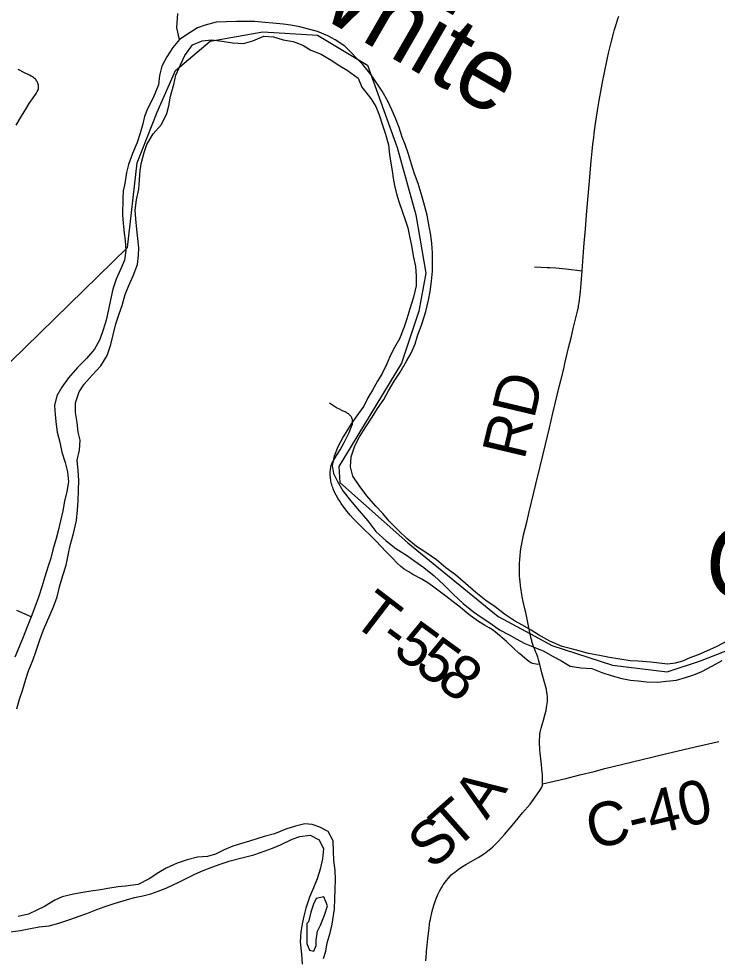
# Model space of a CAD drawing. Extents: x 1451455 to 1749751, y 218250 to 574981.
# Drawn here: x 1570249 to 1575046, y 361334 to 367778 of the extents above; entities that cross this region are included whole.
import ezdxf

# ---------------------------------------------------------------- set-up
doc = ezdxf.new("R2010")
doc.units = 0
for name, color, linetype in [('GM_X_County_Road', 7, 'Continuous'), ('GM_X_County_Road_Text', 7, 'Continuous'), ('GM_X_Major_River', 7, 'Continuous'), ('GM_X_Major_River_Text', 7, 'Continuous'), ('GM_X_Minor_River', 7, 'Continuous'), ('GM_X_Township', 7, 'Continuous'), ('GM_X_Township_Road', 7, 'Continuous'), ('GM_X_Township_Road_Text', 7, 'Continuous')]:
    doc.layers.add(name, color=color, linetype=linetype)

msp = doc.modelspace()

# ---------------------------------------------------------------- linework, layer by layer
at = {"layer": 'GM_X_County_Road'}
for points in [[(1574117.6, 366048), (1574129.7, 366208.3), (1574132, 366238.3), (1574140.5, 366333.9), (1574149, 366431.5), (1574166.7, 366638), (1574180.6, 366800.2), (1574186.9, 366870.1), (1574192.2, 366918.3), (1574197.5, 366963), (1574200.9, 366990.4), (1574209.8, 367060.3), (1574224.9, 367161.1), (1574234, 367216.4), (1574250.2, 367304.9), (1574260.1, 367354.7), (1574266.5, 367386.3), (1574292.9, 367510.9), (1574299.9, 367541.4), (1574318, 367615.4), (1574336.2, 367687.5), (1574341, 367705.5), (1574348.6, 367732), (1574355.5, 367754.1), (1574363.8, 367778.2), (1574370.3, 367796.1)], [(1573771.8, 363509), (1573768.4, 363522.6), (1573756.4, 363575.3), (1573749.3, 363610.3), (1573730.9, 363700.2), (1573724.4, 363727.4), (1573713.2, 363776.3), (1573706.9, 363808.2), (1573703.5, 363826.8), (1573701.5, 363839.4), (1573698.9, 363857), (1573697.3, 363868.9), (1573694.8, 363888.4), (1573692, 363912), (1573689.8, 363932.8), (1573688.5, 363950.7), (1573687.7, 363966.5), (1573687.3, 363981.9), (1573687.1, 364004.3), (1573688.6, 364039.6), (1573690.2, 364062.6), (1573692.6, 364093.7), (1573695.8, 364120.9), (1573700.2, 364151.1), (1573703.8, 364173.2), (1573710.6, 364209.6), (1573715.9, 364234.5), (1573737.3, 364320.4), (1573754.5, 364392.3), (1573801.2, 364583.3), (1573830.2, 364702.9), (1573866.3, 364854.8), (1573894.1, 364969.8), (1573917.8, 365069.4), (1573963.8, 365260.9), (1573971.9, 365295.1), (1573991.3, 365375.4), (1573999.3, 365410.9), (1574025.1, 365518.1), (1574042, 365588.1), (1574057.4, 365651.7), (1574080.2, 365742.7), (1574086.9, 365771.3), (1574089.4, 365783), (1574092.2, 365797.1), (1574094.2, 365808.5), (1574097.4, 365828.7), (1574100.9, 365848.9), (1574105.7, 365884.4), (1574108, 365905.7), (1574111.7, 365959.8), (1574117.6, 366048)], [(1573826.9, 363344.4), (1573819.1, 363375.5), (1573813.3, 363395.3), (1573808.6, 363409), (1573804.3, 363420.3), (1573798.6, 363434.1), (1573792.9, 363447.2), (1573787, 363461.4), (1573782, 363474.8), (1573777.5, 363488.1), (1573773.5, 363502.6), (1573771.8, 363509)], [(1573846.9, 362525.7), (1573846.6, 362544.5), (1573845.9, 362567.4), (1573844.8, 362588.1), (1573843.8, 362604.1), (1573841.8, 362626.1), (1573838.5, 362656.7), (1573830.9, 362734.4), (1573828.6, 362758.4), (1573826.9, 362777.6), (1573826.2, 362790.6), (1573825.7, 362805), (1573825.6, 362812.2), (1573826, 362828.2), (1573827, 362846.5), (1573828.5, 362863.4), (1573830.8, 362878.7), (1573832.7, 362888.3), (1573837, 362906.7), (1573841.5, 362923.3), (1573852.5, 362961.2), (1573864.8, 363004.4), (1573870.3, 363027.8), (1573874.3, 363048.1), (1573876.7, 363063.1), (1573878.4, 363076.9), (1573879.4, 363089.8), (1573880, 363102.5), (1573880, 363111.4), (1573879.8, 363124.7), (1573878.7, 363137.4), (1573876.7, 363153), (1573872.8, 363173.3), (1573862.8, 363212.8), (1573841.1, 363287.7), (1573826.9, 363344.4)], [(1573846.9, 362525.7), (1574006, 362562), (1574101.6, 362585.4), (1574200.3, 362610.2), (1574273.2, 362628.9), (1574396.8, 362660), (1574530.8, 362692.2), (1574597.8, 362708.1), (1574632.9, 362716.5), (1574699.6, 362732.7), (1574807.6, 362759), (1574893.9, 362778.3), (1575057.1, 362814.2)], [(1573421.6, 362030.4), (1573446.5, 362046), (1573470.6, 362063.4), (1573488.6, 362077.9), (1573504.3, 362091.7), (1573517.9, 362104.6), (1573543.2, 362130.5), (1573584.9, 362177.1), (1573648.5, 362252.4), (1573709.5, 362325.3), (1573760.2, 362385.7), (1573784.4, 362417), (1573810.6, 362455.1), (1573831.4, 362486.2), (1573838.3, 362497.9), (1573842.9, 362507.9), (1573845.6, 362516.4), (1573846.9, 362525.7)], [(1573045.3, 361309.2), (1573049.1, 361361.5), (1573050, 361374.6), (1573051.7, 361394.2), (1573058.3, 361462.1), (1573067, 361532.8), (1573070.5, 361559.8), (1573073.3, 361579.5), (1573075.7, 361592.7), (1573078.7, 361608.3), (1573083, 361628.3), (1573088.3, 361649.5), (1573100, 361690.1), (1573113.8, 361729.9), (1573130.4, 361768.6), (1573139.5, 361787.2), (1573147.9, 361803.3), (1573156.4, 361817.6), (1573164.8, 361831), (1573172.9, 361843.2), (1573183.5, 361857.5), (1573199.7, 361877.7), (1573209.4, 361888.7), (1573219.8, 361899.2), (1573230.6, 361909.2), (1573242.8, 361919.1), (1573254.9, 361928.2), (1573267.6, 361937.3), (1573289.2, 361951.7), (1573319.7, 361970.5), (1573404.7, 362019.8), (1573421.6, 362030.4)]]:
    msp.add_lwpolyline(points, dxfattribs=at)
at = {"layer": 'GM_X_Major_River'}
for points in [[(1572744.4, 367281.3), (1572669.8, 367392.4), (1572611.2, 367463.4), (1572489.6, 367589.6), (1572422.5, 367632.8), (1572371.1, 367661.7), (1572301.8, 367691), (1572238.2, 367708.1), (1572178.5, 367723.1), (1572116.8, 367734.2), (1572065, 367741.1), (1571993.3, 367748.3), (1571941.4, 367753.3), (1571867.7, 367760.5), (1571815.7, 367759.4), (1571743.8, 367758.7), (1571673.9, 367757.9), (1571606, 367755.1), (1571529.7, 367734.4), (1571477.4, 367715.3), (1571426.9, 367684.1), (1571354.2, 367635.4), (1571307.3, 367582.2), (1571266.1, 367516.8), (1571231, 367453.4), (1571215.9, 367389.6), (1571208.7, 367323.7)], [(1571314.6, 367325.9), (1571327.8, 367391.7), (1571361, 367461.2), (1571390.1, 367526.7), (1571443.4, 367599.8), (1571509.8, 367626.7), (1571573.8, 367633.6), (1571645.5, 367624.3), (1571717.2, 367613.1), (1571793, 367607.8), (1571857.3, 367626.6), (1571931.7, 367659.4), (1571997.6, 367654.2), (1572065.1, 367633), (1572134.8, 367621.8), (1572200.2, 367596.7), (1572255.5, 367563.7), (1572324.9, 367534.5), (1572394, 367493.2), (1572453.2, 367454.2), (1572504.6, 367425.3), (1572579.5, 367369.9), (1572604.3, 367309.5)], [(1571208.7, 367323.7), (1571172, 367235.5), (1571134.5, 367160.1), (1571113.6, 367108.4), (1571100.6, 367056.6), (1571083.4, 366992.8), (1571062.2, 366929.1), (1571030.8, 366853.6), (1571003.4, 366778), (1570990.3, 366722.1), (1570977, 366648.3), (1570966, 366596.4), (1570963, 366544.4), (1570960.9, 366430.2), (1570965.9, 366376.1), (1570972.6, 366305.9), (1570979.7, 366255.7), (1570984.5, 366187.5), (1570975.3, 366121.6), (1570948, 366056), (1570918.8, 365990.4), (1570895.5, 365922.7), (1570880.1, 365848.9), (1570864.9, 365781.1), (1570849.5, 365709.3), (1570828.3, 365641.5), (1570805, 365575.9), (1570769.8, 365508.4), (1570714.5, 365445.3), (1570653.4, 365384.3), (1570592, 365313.3), (1570544.7, 365248.1), (1570511.6, 365188.6), (1570494.4, 365122.8), (1570499.2, 365058.7), (1570506, 364992.5), (1570513, 364940.2), (1570531.8, 364869.8), (1570544.5, 364801.5), (1570567.2, 364731), (1570584.1, 364666.6), (1570590.8, 364598.4), (1570579.6, 364532.5), (1570564.3, 364464.7), (1570551.1, 364398.8), (1570535.9, 364331), (1570520.6, 364261.2), (1570505.6, 364209.4), (1570484.1, 364131.7), (1570469, 364073.8), (1570452, 364020.1), (1570426.5, 363938.4), (1570409.5, 363884.6), (1570386, 363807), (1570358.7, 363737.4), (1570333.5, 363671.7), (1570308.2, 363602.1), (1570278.9, 363532.5), (1570251.6, 363464.9), (1570222.3, 363395.3)], [(1570235.8, 363040.6), (1570255, 363106.3), (1570274.1, 363166.1), (1570297.6, 363243.8), (1570316.7, 363301.5), (1570348.1, 363379), (1570369.2, 363438.8), (1570394.6, 363512.4), (1570419.9, 363582), (1570442.9, 363633.7), (1570463.9, 363687.4), (1570488.9, 363741), (1570512.2, 363808.7), (1570529.5, 363876.5), (1570553, 363956.2), (1570574.3, 364025.9), (1570589.8, 364105.7), (1570602.8, 364161.6), (1570626.3, 364243.2), (1570646, 364333), (1570653.4, 364407), (1570656.5, 364467), (1570659.8, 364541.1), (1570661.1, 364607.1), (1570658.3, 364675.3), (1570649.6, 364747.5), (1570666.9, 364815.3), (1570670.2, 364885.3), (1570657.2, 364939.7), (1570650.4, 365005.9), (1570639.6, 365074.2), (1570638.9, 365140.3), (1570664.3, 365215.9), (1570699.3, 365269.4), (1570752.5, 365330.5), (1570813.7, 365395.5), (1570857.1, 365466.8), (1570880.5, 365540.5), (1570897.7, 365608.3), (1570917.1, 365684), (1570938.4, 365751.7), (1570959.5, 365809.4), (1570980.9, 365885.1), (1571006.1, 365946.8), (1571035.3, 366012.3), (1571064.8, 366089.9), (1571072, 366155.9), (1571072.9, 366205.9), (1571068.1, 366270.1), (1571061.2, 366332.3), (1571052.5, 366404.6), (1571049.6, 366464.7), (1571056.9, 366534.6), (1571074.3, 366608.4), (1571079.5, 366672.4), (1571082.7, 366738.5), (1571091.7, 366790.4), (1571111, 366860.1), (1571128, 366915.9), (1571173.4, 366987.2), (1571228.6, 367052.3), (1571266.1, 367127.7), (1571281, 367179.5), (1571292.3, 367247.4), (1571314.6, 367325.9)], [(1572604.3, 367309.5), (1572667.4, 367230.6), (1572700.4, 367175.9), (1572723.4, 367119.5), (1572748.1, 367048.9), (1572767, 366986.5), (1572787.6, 366912), (1572796.4, 366845.8), (1572805.3, 366787.5), (1572814.4, 366735.3), (1572819.4, 366683.1), (1572828.5, 366632.9), (1572843.5, 366576.5), (1572860.5, 366524.2), (1572881.3, 366457.7), (1572902.3, 366397.2), (1572921.3, 366342.8), (1572934, 366274.5), (1572947.1, 366222.2), (1572957.8, 366149.9), (1572974.4, 366077.5), (1572979.2, 366011.3), (1572978, 365945.3), (1572960.5, 365865.5), (1572935, 365785.8), (1572913.8, 365718.1), (1572894.6, 365656.4), (1572863.2, 365580.8), (1572830.1, 365521.3), (1572803.1, 365467.8), (1572777.9, 365408.1), (1572744.7, 365342.6), (1572713.7, 365289.1), (1572678.5, 365227.7), (1572645.5, 365174.2), (1572618.4, 365118.6), (1572583.5, 365067.2), (1572532.1, 364996), (1572476.4, 364906.9), (1572441.1, 364839.4), (1572415.9, 364775.8), (1572400.7, 364710), (1572411.7, 364655.7), (1572434.8, 364605.2), (1572475.6, 364536.4), (1572526.4, 364469.4), (1572587.2, 364400.2), (1572646, 364331), (1572700.7, 364257.9), (1572771.5, 364192.6), (1572838.7, 364141.3), (1572917.8, 364089.8), (1572969.2, 364052.8), (1573030.4, 364009.7), (1573101.4, 363952.3), (1573168.4, 363891), (1573235.2, 363823.7), (1573300.2, 363762.5), (1573373.2, 363705.1), (1573424.6, 363670.1), (1573491.8, 363624.8), (1573551.1, 363581.7), (1573616.5, 363548.5), (1573670, 363517.5), (1573723.5, 363488.5), (1573793.1, 363461.2), (1573854.7, 363436), (1573914.1, 363400.9), (1573971.6, 363371.8), (1574035, 363332.6), (1574108.8, 363321.3), (1574184.8, 363315.9), (1574254.4, 363288.6), (1574324, 363265.3), (1574389.8, 363248.1), (1574449.6, 363237), (1574503.6, 363232.1), (1574561.5, 363225), (1574637.6, 363223.6), (1574697.7, 363228.5), (1574765.9, 363237.3), (1574828.3, 363254.2), (1574884.7, 363273.2), (1574941.2, 363296.3)], [(1574856.8, 363389.9), (1574806.4, 363366.8), (1574756.1, 363353.7), (1574705.9, 363346.6), (1574648, 363353.6), (1574590, 363360.7), (1574502.1, 363366.3), (1574448.1, 363369.2), (1574364.2, 363382.8), (1574306.3, 363391.8), (1574238.5, 363405.1), (1574162.7, 363420.5), (1574104.9, 363435.5), (1574035.2, 363454.8), (1573981.4, 363467.8), (1573896, 363505.4), (1573818.7, 363548.8), (1573767.3, 363579.8), (1573707.8, 363614.9), (1573654.3, 363643.9), (1573585.1, 363689.2), (1573520, 363740.5), (1573456.7, 363783.7), (1573387.7, 363839), (1573316.7, 363900.3), (1573247.7, 363959.7), (1573182.6, 364008.9), (1573117.5, 364062.2), (1573044.4, 364113.5), (1572981.1, 364154.8), (1572914, 364210), (1572857, 364265.1), (1572794.1, 364328.3), (1572749, 364381.2), (1572701.9, 364432.1), (1572639.1, 364501.4), (1572586.4, 364572.4), (1572543.5, 364637.3), (1572526.7, 364701.7), (1572531.9, 364769.7), (1572557.4, 364845.3), (1572588.5, 364906.8), (1572633.8, 364976.1), (1572675.1, 365041.5), (1572712.2, 365102.9), (1572755.4, 365164.2), (1572788.5, 365223.7), (1572827.8, 365289.1), (1572869, 365352.4), (1572912.4, 365427.7), (1572943.5, 365483.2), (1572970.7, 365546.8), (1572987.7, 365600.6), (1573017.2, 365680.2), (1573044.8, 365767.8), (1573062.3, 365845.6), (1573073.4, 365905.5), (1573082.7, 365975.4), (1573090, 366045.4), (1573091.1, 366107.5), (1573090.3, 366171.5), (1573085.5, 366235.7), (1573078.5, 366291.9), (1573067.6, 366352.2), (1573053, 366430.6), (1573030.5, 366515.1), (1573013.7, 366577.5), (1572993, 366648), (1572966.1, 366712.5), (1572945.4, 366781), (1572924.6, 366847.5), (1572901.8, 366916), (1572882.7, 366966.4), (1572861.9, 367030.8), (1572837, 367095.4), (1572812.1, 367153.9), (1572783.1, 367212.5), (1572744.4, 367281.3)], [(1575117.3, 363507.4), (1575042.4, 363466.7), (1574971.8, 363435.9), (1574915.3, 363410.9), (1574856.8, 363389.9)], [(1574941.2, 363296.3), (1575014, 363335), (1575078.7, 363371.9)], [(1572342.3, 361324.3), (1572357.3, 361376.1), (1572368.3, 361432), (1572387.6, 361501.8), (1572400.7, 361561.6), (1572416.7, 361665.5), (1572420, 361735.5), (1572421.2, 361801.6), (1572424.4, 361865.6), (1572421.6, 361931.8), (1572412.8, 361998), (1572410, 362062.1), (1572409.3, 362132.2), (1572374.4, 362197), (1572316.9, 362228), (1572265.2, 362245), (1572213.2, 362249.9), (1572150.9, 362235), (1572084.4, 362212.2), (1572005.8, 362181.6), (1571935.3, 362162.8), (1571885, 362147.7), (1571834.6, 362130.6), (1571772.2, 362111.7), (1571719.9, 362096.6), (1571659.4, 362071.7), (1571600.8, 362042.7), (1571544.4, 362025.7), (1571476.3, 362020.9), (1571405.8, 362002.1), (1571337.4, 361979.3), (1571262.6, 361944.6), (1571212.1, 361915.5), (1571145.2, 361872.6), (1571070.4, 361833.9), (1570982.1, 361821.5), (1570932, 361818.4), (1570861.7, 361805.6), (1570811.4, 361796.5), (1570743.2, 361787.7), (1570689, 361778.7), (1570624.7, 361765.8), (1570548.3, 361749.2), (1570497.8, 361726), (1570425, 361683.3), (1570374.4, 361656.2), (1570315.9, 361629.2), (1570245.5, 361614.4)], [(1570191.5, 361507.2), (1570261.7, 361518), (1570318, 361529), (1570390.3, 361541.7), (1570458.6, 361550.5), (1570524.9, 361567.3), (1570599.5, 361592), (1570664, 361614.9), (1570716.4, 361634), (1570784.9, 361660.8), (1570835.3, 361679.9), (1570903.8, 361702.7), (1570990.3, 361727.2), (1571044.7, 361744.2), (1571101, 361755.2), (1571155.3, 361770.3), (1571205.7, 361787.4), (1571266.2, 361810.4), (1571349, 361848.9), (1571407.6, 361879.9), (1571458.1, 361905), (1571514.6, 361930.1), (1571575.1, 361953), (1571631.6, 361974), (1571700, 361994.8), (1571780.5, 362017.4), (1571863, 362038), (1571941.5, 362064.6), (1571991.9, 362081.7), (1572046.4, 362104.7), (1572127.2, 362145.3), (1572179.6, 362162.4), (1572249.8, 362173.2), (1572311.3, 362140), (1572342.2, 362077.4), (1572334.9, 362009.4), (1572319.6, 361939.6), (1572298.3, 361871.9), (1572273.2, 361810.2), (1572246, 361746.6), (1572220.6, 361671), (1572207.5, 361615.2), (1572194.6, 361563.3), (1572185.5, 361507.4), (1572182.3, 361439.4), (1572190.7, 361355.1), (1572195.5, 361286.9)], [(1572226.6, 361564.8), (1572227.1, 361484.6), (1572228.1, 361428.5), (1572245.3, 361382.1), (1572275.2, 361375.6), (1572291.9, 361413.4), (1572290.6, 361451.4), (1572301.7, 361513.3), (1572322.5, 361553), (1572349.8, 361622.6), (1572369, 361686.3), (1572344.1, 361748.9)], [(1572344.1, 361748.9), (1572291.9, 361737.8), (1572273.1, 361698.1), (1572256.1, 361644.3), (1572238.8, 361576.5), (1572226.6, 361564.8)]]:
    msp.add_lwpolyline(points, dxfattribs=at)
at = {"layer": 'GM_X_Minor_River'}
for points in [[(1571354.2, 367635.4), (1571335.1, 367716.7), (1571342.7, 367814.6)], [(1570333.8, 363672.4), (1570236.6, 363714)]]:
    msp.add_lwpolyline(points, dxfattribs=at)
at = {"layer": 'GM_X_Township'}
msp.add_lwpolyline([(1568987.4, 364245.4), (1570997.2, 366208.8), (1571063.4, 366788.4), (1571199.8, 367137.3), (1571326.2, 367422.5), (1571562.8, 367625.4), (1571925.9, 367688.4), (1572301, 367666), (1572643.9, 367459.1), (1572848.5, 366894.7), (1572976.9, 366431.5), (1573045.1, 366032.4), (1572996.9, 365769.7), (1572878.6, 365412.7), (1572447.3, 364702.8), (1572455.3, 364594.5), (1572920.7, 364179.4), (1573542.4, 363674.1), (1573792.7, 363538.7), (1573909.5, 363475.5), (1574326.6, 363339.2), (1574701.7, 363293.1), (1574930.4, 363369.3), (1575393.7, 363549.8)], dxfattribs=at)
msp.add_lwpolyline([(1568987.4, 364245.4), (1570997.2, 366208.8), (1571063.4, 366788.4), (1571199.8, 367137.3), (1571326.2, 367422.5), (1571562.8, 367625.4), (1571925.9, 367688.4), (1572301, 367666), (1572643.9, 367459.1), (1572848.5, 366894.7), (1572976.9, 366431.5), (1573045.1, 366032.4), (1572996.9, 365769.7), (1572878.6, 365412.7), (1572447.3, 364702.8), (1572455.3, 364594.5), (1572920.7, 364179.4), (1573542.4, 363674.1), (1573792.7, 363538.7), (1573909.5, 363475.5), (1574326.6, 363339.2), (1574701.7, 363293.1), (1574930.4, 363369.3), (1575393.7, 363549.8)], dxfattribs=at)
at = {"layer": 'GM_X_Township_Road'}
for points in [[(1570232.6, 367048), (1570268.9, 367110.2), (1570285.9, 367139.7), (1570297.1, 367158.3), (1570321.3, 367197.3), (1570331.9, 367213), (1570343.7, 367229.6), (1570368.7, 367264.2), (1570376.8, 367278.5), (1570382.5, 367289.6), (1570384, 367297.7), (1570384.8, 367303.4), (1570385.2, 367310.7), (1570385, 367316.4), (1570384.4, 367323.3), (1570382.7, 367330.2), (1570380.9, 367335.8), (1570378.5, 367341.6), (1570375.3, 367348), (1570372.1, 367353), (1570367.9, 367358.8), (1570363.9, 367363.3), (1570357.9, 367368.9), (1570351.6, 367374.1), (1570343.6, 367379.7), (1570335.1, 367384.9), (1570324.1, 367391), (1570289.3, 367407.5), (1570245.5, 367430.9)], [(1573791.6, 366075.9), (1573879.1, 366070.7), (1573899.7, 366069.7), (1573936.7, 366067.4), (1573960.8, 366065.4), (1574005.3, 366060.8), (1574117.6, 366048)], [(1572388.4, 364642.8), (1572388.2, 364649.8), (1572388.4, 364658.9), (1572388.8, 364668.1), (1572389.7, 364680), (1572390.6, 364687.2), (1572391.8, 364695.6), (1572393.1, 364703.2), (1572394.9, 364710.6), (1572396.6, 364715.8), (1572398.8, 364721), (1572402.5, 364728.4), (1572406.2, 364735.6), (1572432.3, 364778.2), (1572457.3, 364818.6), (1572470.7, 364842.4), (1572484.2, 364868), (1572502.4, 364904.1), (1572517.2, 364936.2), (1572530.6, 364966.7), (1572535, 364977.8), (1572538.5, 364988.2), (1572540.4, 364995), (1572541.4, 365000.9), (1572542, 365006.2), (1572542.2, 365010.6), (1572542, 365015.9), (1572541.4, 365020.5), (1572540.1, 365026.5), (1572538.4, 365032.1), (1572536.3, 365038), (1572534, 365042.4), (1572531.5, 365046.6), (1572528.4, 365050.9), (1572525.8, 365054.1), (1572523.1, 365056.9), (1572520.5, 365059.6), (1572517.1, 365062.4), (1572513.2, 365065.3), (1572507.8, 365068.8), (1572502.9, 365071.6), (1572498.6, 365073.9), (1572489.7, 365078.2), (1572478.2, 365083.4), (1572466.9, 365088.9), (1572452, 365096.4), (1572431.6, 365107.8), (1572384, 365137.6)], [(1573567.1, 363530.1), (1573559.7, 363536.9), (1573539.7, 363553.5), (1573522, 363567.5), (1573511.3, 363575.5), (1573502.8, 363581.7), (1573491.8, 363588.5), (1573479.3, 363596.5), (1573448.5, 363615), (1573406.6, 363639.9), (1573391.1, 363650.2), (1573374.2, 363662.2), (1573340.5, 363688.3), (1573282.2, 363736.1), (1573181.8, 363814.3), (1573128.1, 363855.5), (1573091.4, 363882.9), (1573058.7, 363904.8), (1573036.1, 363918.8), (1573016.6, 363930.3), (1572956.6, 363963.1), (1572927.6, 363979.6), (1572912.4, 363988.7), (1572897, 363998.5), (1572873.9, 364016.6), (1572847.3, 364041.1), (1572817.4, 364071.3), (1572797.3, 364092.4), (1572773, 364118), (1572701, 364193.2), (1572661.6, 364232.4), (1572624.1, 364269.1), (1572598.6, 364294.7), (1572546.9, 364347.2), (1572526.1, 364369.8), (1572504.8, 364395.4), (1572488.8, 364415.8), (1572463.6, 364449.6), (1572453.6, 364464.8), (1572443.2, 364481.8), (1572429.4, 364506.8), (1572418, 364528.6), (1572413.1, 364539.2), (1572408.6, 364549.6), (1572405.1, 364558.7), (1572401.6, 364568.5), (1572399, 364577.1), (1572396.9, 364585.4), (1572394.9, 364593.9), (1572393.2, 364602.4), (1572391.6, 364611.6), (1572390.2, 364621.1), (1572389.2, 364630.3), (1572388.5, 364641), (1572388.4, 364642.8)], [(1573683.2, 363422.7), (1573648.3, 363454.3), (1573598.2, 363501.5), (1573567.1, 363530.1)], [(1573826.9, 363344.4), (1573803.5, 363346.7), (1573788.3, 363348.9), (1573779.8, 363350.7), (1573776.2, 363351.7), (1573772.5, 363353), (1573766.3, 363355.8), (1573759.8, 363360.2), (1573753.2, 363365.2), (1573724.8, 363387.4), (1573687.2, 363419.1), (1573683.2, 363422.7)]]:
    msp.add_lwpolyline(points, dxfattribs=at)

# ---------------------------------------------------------------- texts
at = {"layer": 'GM_X_County_Road_Text'}
for s, rotation, p in [('RD', 76.67551, (1573720.7, 364742.4)), ('A', 55.59877, (1573462.7, 362271.4)), ('C-40', 13.54901, (1574186.3, 362071.6)), ('T', 41.51146, (1573241.5, 362062.5)), ('S', 41.5558, (1573090.1, 361928.2))]:
    msp.add_text(s, height=300, rotation=rotation, dxfattribs=at).set_placement(p)
at = {"layer": 'GM_X_Major_River_Text'}
for s, height, rotation, p in [('White', 500.02, 329.99559, (1572039.8, 367953.3)), ('Oak', 500, 354.99995, (1574948.3, 363814.8))]:
    msp.add_text(s, height=height, rotation=rotation, dxfattribs=at).set_placement(p)
at = {"layer": 'GM_X_Township_Road_Text'}
for s, rotation, p in [('T', 322.59525, (1572524.6, 363635.3)), ('5', 323.85666, (1572807.9, 363421.7)), ('-', 323.67756, (1572707.8, 363495.2)), ('5', 323.91733, (1572957.4, 363312.5)), ('8', 323.93133, (1573106.8, 363203.6))]:
    msp.add_text(s, height=300, rotation=rotation, dxfattribs=at).set_placement(p)

doc.saveas('drawing.dxf')
